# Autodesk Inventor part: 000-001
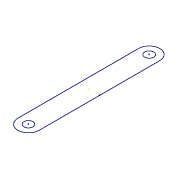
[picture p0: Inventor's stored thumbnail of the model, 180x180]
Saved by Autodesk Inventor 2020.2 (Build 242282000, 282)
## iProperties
Created: 2015-05
Part Number: 000-001
Material: Ogólny
Document SubType Name: Modeling
Designer: F.Stasiak
Density: 1 g/cm^3
Appearance: Domyślna
Manager: www.cadconsulting.pl
Company: Fabian Stasiak CAD Consulting
Author: F.Stasiak
Subject: Zbiór ćwiczeń. Autodesk Inventor 2020. Kurs podstawowy
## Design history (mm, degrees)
node "Bloki"
  sketch "Płyta zawieszenia"
    geometry: L1 (-157.394, -400)-(-157.394, 400); L2 (-17.394, -400)-(-17.394, 400); C1 r 30 at (-87.394, 400); C2 r 30 at (-87.394, -400); A1 r 70 centre (-87.394, -400) between (-157.394, -400) and (-17.394, -400); A2 r 70 centre (-87.394, 400) between (-17.394, 400) and (-157.394, 400); 1 further point
    constraints: 4 centre point, 4 end point, 4 point on circle, 1 other
sketch "Szkic1"
  geometry: 2 further points
  constraints: 2 horizontal alignment, 3 other
  node "Płyta zawieszenia:1"
